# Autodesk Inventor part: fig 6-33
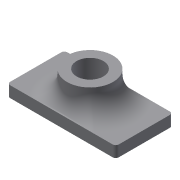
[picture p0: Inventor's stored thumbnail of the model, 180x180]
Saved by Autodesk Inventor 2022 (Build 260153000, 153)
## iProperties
Created: 2004-05
Part Number: fig 6-33
Document SubType Name: Modeling
Designer: CADCIM Technologies
Manufacturer: Standard
Standards Organization: Custom
Density: 1 g/cm^3
Material: Generic
Appearance: Default
Author: CADCIM Technologies
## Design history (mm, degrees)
sketch "Sketch1"
  geometry: L1 (-39.276, -18.692)-(33.721, -18.692); L2 (33.721, -18.692)-(33.721, 19.728); L3 (33.721, 19.728)-(-39.276, 19.728); L4 (-39.276, 19.728)-(-39.276, -18.692)
  constraints: 8 end point, 2 parallel, 1 horizontal, 1 perpendicular
extrude "Extrusion1" new body sketch "Sketch1" distance "d0" = 7.5; taper "d1" = 0 deg
fillet "Fillet1" dims "d2" = 2
sketch "Sketch2"
  geometry: C1 r 15.456 at (-2.778, 0.518)
  constraints: 1 centre point
extrude "Extrusion2" join sketch "Sketch2" distance "d3" = 17.25; taper "d4" = 0 deg
hole "Hole1" diameter "d8" = 18; stored, may be unused: countersink angle "d12" = 90 deg, drill point angle "d14" = 118 deg; dims "d6" = 10, "d7" = 10, "d9" = 6, "d10" = 4, "d11" = 2, "d13" = 8
fillet "Fillet2" dims "d5" = 14
body "Solid1"
